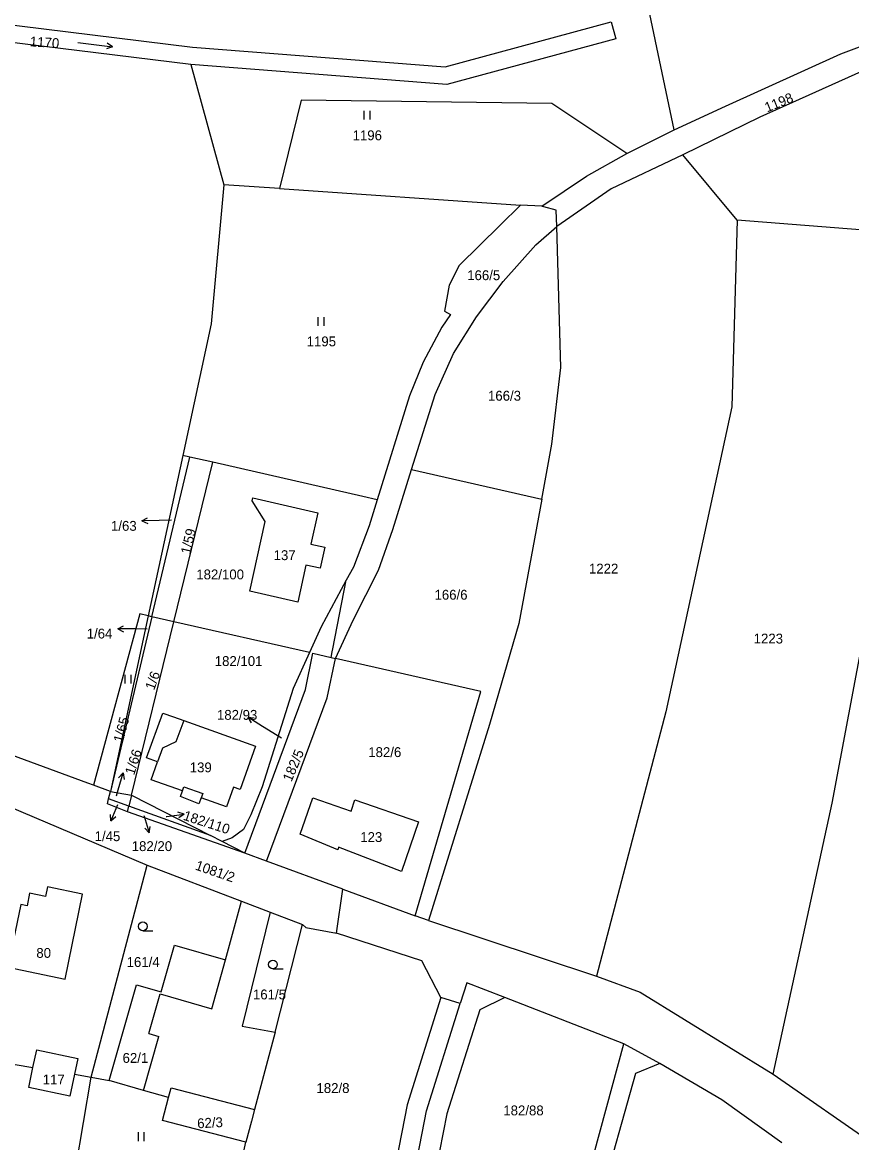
# Model space of a CAD drawing. Extents: x -746176 to -739709, y -1128407 to -1124482.
# Drawn here: x -742008.2 to -741865.4, y -1126433.2 to -1126240.2 of the extents above; entities that cross this region are included whole.
import ezdxf

# ---------------------------------------------------------------- set-up
doc = ezdxf.new("R2010")
doc.units = 0
for name, color, linetype in [('Hranice parcel', 7, 'Continuous'), ('Parcelní čísla', 7, 'Continuous'), ('Pop  PČ popisy', 7, 'Continuous'), ('Vnitřní kresba', 7, 'Continuous'), ('Značky kultur', 7, 'Continuous')]:
    doc.layers.add(name, color=color, linetype=linetype)

msp = doc.modelspace()

# ---------------------------------------------------------------- linework, layer by layer
at = {"layer": 'Hranice parcel'}
for p, q in [((-741979.16, -1126247.44), (-741973.49, -1126268.18)), ((-741904.1, -1126262.78), (-741895.95, -1126258.73)), ((-741885.09, -1126274.27), (-741894.45, -1126263.02)), ((-741963.91, -1126268.84), (-741973.49, -1126268.18)), ((-741963.91, -1126268.84), (-741922.39, -1126271.67)), ((-741918.69, -1126271.87), (-741922.39, -1126271.67)), ((-741856.86, -1126276.54), (-741885.09, -1126274.27)), ((-741980.55, -1126314.84), (-741986.51, -1126342.46)), ((-741985.86, -1126342.61), (-741979.32, -1126315.12)), ((-741982.09, -1126343.47), (-741975.4, -1126316.01)), ((-741979.32, -1126315.12), (-741980.55, -1126314.84)), ((-741975.4, -1126316.01), (-741979.32, -1126315.12)), ((-741941.15, -1126317.27), (-741918.74, -1126322.36)), ((-741951.16, -1126334.05), (-741952.39, -1126336.34)), ((-741952.39, -1126336.34), (-741956.73, -1126344.37)), ((-741986.51, -1126342.46), (-741993.03, -1126372.73)), ((-741985.86, -1126342.61), (-741993.03, -1126372.73)), ((-741989.38, -1126373.38), (-741982.09, -1126343.47)), ((-741985.86, -1126342.61), (-741986.51, -1126342.46)), ((-741982.09, -1126343.47), (-741985.86, -1126342.61)), ((-741958.73, -1126348.77), (-741982.09, -1126343.47)), ((-741954.27, -1126349.79), (-741951.24, -1126343.21)), ((-741956.73, -1126344.37), (-741958.73, -1126348.77)), ((-741955, -1126349.62), (-741954.27, -1126349.79)), ((-741993.03, -1126372.73), (-741995.94, -1126371.66)), ((-741993.33, -1126374), (-741993.03, -1126372.73)), ((-741989.85, -1126375.26), (-741993.33, -1126374)), ((-741993.03, -1126372.73), (-741989.38, -1126373.38)), ((-741989.38, -1126373.38), (-741989.85, -1126375.26)), ((-741989.38, -1126373.38), (-741975.79, -1126380.32)), ((-741990.09, -1126376.24), (-741989.85, -1126375.26)), ((-741969.88, -1126383.35), (-741990.09, -1126376.24)), ((-741975.79, -1126380.32), (-741989.85, -1126375.26)), ((-741973.78, -1126381.35), (-741975.79, -1126380.32)), ((-741972.03, -1126380.69), (-741973.78, -1126381.35)), ((-741969.88, -1126383.35), (-741973.78, -1126381.35)), ((-741966.13, -1126384.73), (-741969.88, -1126383.35)), ((-741996.32, -1126421.94), (-741986.71, -1126385.43)), ((-741986.71, -1126385.43), (-741970.45, -1126391.64)), ((-741953, -1126389.58), (-741966.13, -1126384.73)), ((-741954.07, -1126397.17), (-741953, -1126389.58)), ((-741953, -1126389.58), (-741940.51, -1126394.18)), ((-741970.45, -1126391.64), (-741965.53, -1126393.52)), ((-741965.53, -1126393.52), (-741959.96, -1126395.65)), ((-741964.66, -1126414.2), (-741959.96, -1126395.65)), ((-741938.23, -1126394.97), (-741940.51, -1126394.18)), ((-741938.23, -1126394.97), (-741909.32, -1126404.54)), ((-741932.77, -1126409.29), (-741936.11, -1126408.24)), ((-741904.57, -1126416.23), (-741925.07, -1126408.25)), ((-741964.66, -1126414.2), (-741968.2, -1126427.52)), ((-741898.42, -1126419.6), (-741904.57, -1126416.23)), ((-741999.2, -1126421.47), (-741996.32, -1126421.94)), ((-741999.11, -1126438.17), (-741996.32, -1126421.94)), ((-741996.32, -1126421.94), (-741993.21, -1126422.56)), ((-741878.88, -1126421.46), (-741852.49, -1126439.8)), ((-741971.96, -1126443.41), (-741969.67, -1126433.17))]:
    msp.add_line(p, q, dxfattribs=at)
for points in [[(-741895.95, -1126258.73), (-741902.39, -1126227.83), (-742032.39, -1126201.61)], [(-741979.16, -1126247.44), (-742018.02, -1126242.67), (-742051.56, -1126236.78), (-742071.8, -1126233.98)], [(-742037.23, -1126236.37), (-742017.58, -1126239.71), (-741978.86, -1126244.46), (-741935.37, -1126247.86), (-741906.75, -1126240.11), (-741905.97, -1126243.01), (-741935.09, -1126250.9), (-741979.16, -1126247.44)], [(-741895.95, -1126258.73), (-741887.06, -1126254.64), (-741867.23, -1126245.63), (-741859.7, -1126242.83), (-741853.68, -1126241.82), (-741840.1, -1126242.23)], [(-741841.74, -1126251.46), (-741852.27, -1126246.05), (-741856.49, -1126246.25), (-741862.01, -1126247.91), (-741881.16, -1126256.56), (-741894.45, -1126263.02)], [(-741904.1, -1126262.78), (-741917.02, -1126254.2), (-741960.14, -1126253.61), (-741963.91, -1126268.84)], [(-741918.69, -1126271.87), (-741911.03, -1126266.72), (-741904.1, -1126262.78)], [(-741894.45, -1126263.02), (-741906.75, -1126268.89), (-741916.15, -1126275.4)], [(-741973.49, -1126268.18), (-741975.66, -1126292.15), (-741980.55, -1126314.84)], [(-741922.39, -1126271.67), (-741925.91, -1126275.15), (-741932.95, -1126282.11), (-741934.69, -1126285.47), (-741935.47, -1126289.95), (-741934.45, -1126290.55), (-741935.93, -1126292.73), (-741939.16, -1126298.76), (-741941.48, -1126304.55), (-741947.05, -1126322.45)], [(-741916.15, -1126275.4), (-741916.23, -1126272.57), (-741918.37, -1126271.96), (-741918.69, -1126271.87)], [(-741941.15, -1126317.27), (-741937.11, -1126304.31), (-741933.93, -1126297.28), (-741929.99, -1126290.94), (-741925.39, -1126284.87), (-741919.74, -1126278.55), (-741916.15, -1126275.4)], [(-741918.74, -1126322.36), (-741917, -1126312.88), (-741915.44, -1126299.69), (-741916.15, -1126275.4)], [(-741885.09, -1126274.27), (-741886, -1126306.44), (-741897.34, -1126359), (-741909.32, -1126404.54)], [(-741878.88, -1126421.46), (-741868.71, -1126374.72), (-741857.4, -1126314.53), (-741856.86, -1126276.54)], [(-741947.05, -1126322.45), (-741949.55, -1126321.88), (-741975.4, -1126316.01)], [(-741951.24, -1126343.21), (-741946.82, -1126334.61), (-741944.36, -1126327.59), (-741941.15, -1126317.27)], [(-741969.03, -1126338.22), (-741966.34, -1126326.2), (-741968.61, -1126322.66), (-741968.49, -1126322.14), (-741957.3, -1126324.7), (-741958.52, -1126330.09), (-741956.07, -1126330.63), (-741956.89, -1126334.27), (-741959.34, -1126333.71), (-741960.77, -1126340.08), (-741969.03, -1126338.22)], [(-741947.05, -1126322.45), (-741948.46, -1126326.96), (-741951.16, -1126334.05)], [(-741918.74, -1126322.36), (-741922.66, -1126343.77), (-741927.73, -1126361.18), (-741938.23, -1126394.97)], [(-741955, -1126349.62), (-741954.81, -1126348.66), (-741954.71, -1126348.16), (-741952.39, -1126336.34)], [(-741986.51, -1126342.46), (-741987.96, -1126342.12), (-741995.94, -1126371.66)], [(-741958.73, -1126348.77), (-741961.57, -1126355.01), (-741966.88, -1126371.94), (-741968.84, -1126376.73), (-741970.09, -1126379.3), (-741972.03, -1126380.69)], [(-741969.88, -1126383.35), (-741959.42, -1126355.18), (-741958.17, -1126348.9), (-741955, -1126349.62)], [(-741966.13, -1126384.73), (-741955.67, -1126356.57), (-741954.27, -1126349.79)], [(-741940.51, -1126394.18), (-741929.25, -1126355.48), (-741954.27, -1126349.79)], [(-741977.77, -1126374.86), (-741980.95, -1126373.62), (-741980.61, -1126372.64), (-741986.02, -1126370.7), (-741984.92, -1126367.63), (-741986.82, -1126366.94), (-741984.02, -1126359.21), (-741982.15, -1126359.85), (-741980.39, -1126360.49), (-741968.02, -1126364.9), (-741970.7, -1126372.41), (-741971.84, -1126372), (-741973.03, -1126375.35), (-741977.37, -1126373.8), (-741977.77, -1126374.86)], [(-741995.94, -1126371.66), (-741996.93, -1126371.29), (-742011.08, -1126366.08), (-742011.25, -1126365.95)], [(-742017.65, -1126371.11), (-742017.02, -1126371.6), (-742014.99, -1126373.44), (-741986.71, -1126385.43)], [(-741990.09, -1126376.24), (-741993.53, -1126374.84), (-741993.33, -1126374)], [(-741958.18, -1126373.85), (-741951.58, -1126376.12), (-741950.91, -1126374.18), (-741939.97, -1126377.94), (-741942.91, -1126386.52), (-741953.71, -1126382.33), (-741953.86, -1126382.76), (-741960.32, -1126380.06), (-741958.18, -1126373.85)], [(-742003.87, -1126389.15), (-742004.21, -1126390.8), (-742006.94, -1126390.24), (-742007.38, -1126392.41), (-742008.47, -1126392.19), (-742010.7, -1126403.03), (-742000.83, -1126405.05), (-741997.82, -1126390.4), (-742003.87, -1126389.15)], [(-741993.21, -1126422.56), (-741988.52, -1126406.06), (-741984.26, -1126407.27), (-741981.98, -1126399.24), (-741973.18, -1126401.74), (-741970.45, -1126391.64)], [(-741965.53, -1126393.52), (-741970.31, -1126413.16), (-741964.66, -1126414.2)], [(-741959.96, -1126395.65), (-741959.39, -1126396.19), (-741954.07, -1126397.17)], [(-741936.11, -1126408.24), (-741939.36, -1126401.91), (-741954.07, -1126397.17)], [(-741909.32, -1126404.54), (-741901.76, -1126407.3), (-741878.88, -1126421.46)], [(-741925.07, -1126408.25), (-741931.64, -1126405.69), (-741932.77, -1126409.29)], [(-741954.32, -1126508.73), (-741938.56, -1126427.78), (-741932.77, -1126409.29)], [(-741936.11, -1126408.24), (-741941.9, -1126426.74), (-741946.15, -1126448.52)], [(-741925.07, -1126408.25), (-741929.41, -1126410.36), (-741935.06, -1126428.26), (-741937.58, -1126441.15)], [(-742024.68, -1126414.24), (-742015.91, -1126416.77), (-742016.26, -1126418.65), (-742006.36, -1126420.29)], [(-741912.45, -1126446.2), (-741911.72, -1126442.48), (-741904.57, -1126416.23)], [(-742006.36, -1126420.29), (-742005.72, -1126417.27), (-741998.63, -1126418.76), (-741999.2, -1126421.47)], [(-741999.2, -1126421.47), (-741999.99, -1126425.22), (-742007.08, -1126423.73), (-742006.36, -1126420.29)], [(-741898.42, -1126419.6), (-741902.57, -1126421.34), (-741908.84, -1126443.59), (-741914.46, -1126471.66), (-741921.58, -1126508.41), (-741929.05, -1126550.68), (-741935.86, -1126591.95), (-741938.82, -1126591.67)], [(-741877.38, -1126433.3), (-741887.7, -1126425.84), (-741898.42, -1126419.6)], [(-741983.01, -1126425.46), (-741987.35, -1126424.23), (-741993.21, -1126422.56)], [(-741983.01, -1126425.46), (-741982.58, -1126423.8), (-741968.2, -1126427.52)], [(-741969.67, -1126433.17), (-741984.04, -1126429.45), (-741983.01, -1126425.46)], [(-741968.2, -1126427.52), (-741968.72, -1126429.53), (-741969.67, -1126433.17)]]:
    msp.add_lwpolyline(points, dxfattribs=at)
at = {"layer": 'Pop  PČ popisy'}
for p, q in [((-741987.6, -1126326.08), (-741986.61, -1126325.56)), ((-741984.6, -1126326.03), (-741987.6, -1126326.08)), ((-741987.6, -1126326.08), (-741986.59, -1126326.57)), ((-741982.49, -1126326), (-741984.6, -1126326.03)), ((-741991.75, -1126344.68), (-741990.74, -1126344.19)), ((-741988.75, -1126344.73), (-741991.75, -1126344.68)), ((-741991.75, -1126344.68), (-741990.76, -1126345.2)), ((-741986.71, -1126344.75), (-741988.75, -1126344.73)), ((-741966.82, -1126361.51), (-741969.36, -1126359.92)), ((-741969.36, -1126359.92), (-741968.25, -1126360.03)), ((-741969.36, -1126359.92), (-741968.78, -1126360.88)), ((-741963.58, -1126363.54), (-741966.82, -1126361.51)), ((-741991.68, -1126372.43), (-741990.85, -1126369.54)), ((-741990.85, -1126369.54), (-741991.61, -1126370.37)), ((-741990.85, -1126369.54), (-741990.65, -1126370.65)), ((-741991.98, -1126373.5), (-741991.68, -1126372.43)), ((-741991.82, -1126375.03), (-741992.94, -1126377.81)), ((-741980.33, -1126376.66), (-741981.39, -1126376.29)), ((-741992.94, -1126377.81), (-741993.03, -1126376.7)), ((-741992.94, -1126377.81), (-741992.1, -1126377.07)), ((-741987.25, -1126376.89), (-741987.22, -1126377)), ((-741987.22, -1126377), (-741986.34, -1126379.87)), ((-741983.4, -1126377.04), (-741983.31, -1126377.03)), ((-741983.31, -1126377.03), (-741980.33, -1126376.66)), ((-741980.33, -1126376.66), (-741981.26, -1126377.28)), ((-741986.34, -1126379.87), (-741987.11, -1126379.06)), ((-741986.34, -1126379.87), (-741986.16, -1126378.77))]:
    msp.add_line(p, q, dxfattribs=at)
at = {"layer": 'Vnitřní kresba'}
for p, q in [((-741980.39, -1126360.49), (-741981.73, -1126364.15)), ((-741981.73, -1126364.15), (-741984.06, -1126365.24)), ((-741984.06, -1126365.24), (-741984.92, -1126367.63)), ((-741980.61, -1126372.64), (-741980.36, -1126371.92)), ((-741980.36, -1126371.92), (-741977.1, -1126373.07)), ((-741977.1, -1126373.07), (-741977.37, -1126373.8)), ((-741975.58, -1126410.16), (-741973.18, -1126401.74)), ((-741986.43, -1126414.45), (-741984.48, -1126407.62)), ((-741984.48, -1126407.62), (-741975.58, -1126410.16)), ((-741987.35, -1126424.23), (-741984.7, -1126414.94)), ((-741986.43, -1126414.45), (-741984.7, -1126414.94))]:
    msp.add_line(p, q, dxfattribs=at)
at = {"layer": 'Značky kultur'}
for p, q in [((-741998.62, -1126243.68), (-741992.67, -1126244.41)), ((-741992.67, -1126244.41), (-741993.7, -1126244.78)), ((-741992.67, -1126244.41), (-741993.58, -1126243.79)), ((-741949.31, -1126256.96), (-741949.31, -1126255.46)), ((-741948.31, -1126256.96), (-741948.31, -1126255.46)), ((-741957.22, -1126292.47), (-741957.22, -1126290.97)), ((-741956.22, -1126292.47), (-741956.22, -1126290.97)), ((-741990.47, -1126354.15), (-741990.47, -1126352.65)), ((-741989.47, -1126354.15), (-741989.47, -1126352.65)), ((-741987.45, -1126396.72), (-741985.7, -1126396.72)), ((-741965.03, -1126403.31), (-741963.28, -1126403.31)), ((-741988.21, -1126432.96), (-741988.21, -1126431.46)), ((-741987.21, -1126432.96), (-741987.21, -1126431.46))]:
    msp.add_line(p, q, dxfattribs=at)
for centre in [(-741987.45, -1126395.97), (-741965.03, -1126402.56)]:
    msp.add_circle(centre, 0.75, dxfattribs=at)

# ---------------------------------------------------------------- texts
at = {"layer": 'Parcelní čísla'}
for s, rotation, p in [('1170', 356, (-742006.94, -1126244.31)), ('1198', 22, (-741879.92, -1126255.73)), ('1/59', 77, (-741979.28, -1126331.96)), ('1/6', 70, (-741985.5, -1126355.38)), ('1/65', 75, (-741990.9, -1126364.43)), ('1/66', 72, (-741988.95, -1126370.01)), ('182/5', 67, (-741961.85, -1126371.18)), ('182/110', 342, (-741980.61, -1126377.58)), ('1081/2', 341, (-741978.54, -1126386.16)), ('62/3', 3, (-741978.03, -1126430.78))]:
    msp.add_text(s, height=1.7, rotation=rotation, dxfattribs=at).set_placement(p)
for s, p in [('1196', (-741951.31, -1126260.51)), ('166/5', (-741931.57, -1126284.62)), ('1195', (-741959.22, -1126296.02)), ('166/3', (-741927.99, -1126305.39)), ('1/63', (-741992.92, -1126327.81)), ('137', (-741964.91, -1126332.86)), ('1222', (-741910.6, -1126335.17)), ('182/100', (-741978.23, -1126336.18)), ('166/6', (-741937.2, -1126339.68)), ('1/64', (-741997.11, -1126346.37)), ('1223', (-741882.23, -1126347.23)), ('182/101', (-741975.05, -1126351.11)), ('182/93', (-741974.67, -1126360.38)), ('182/6', (-741948.61, -1126366.8)), ('139', (-741979.36, -1126369.43)), ('1/45', (-741995.74, -1126381.29)), ('123', (-741949.99, -1126381.44)), ('182/20', (-741989.35, -1126383)), ('80', (-742005.78, -1126401.4)), ('161/4', (-741990.23, -1126402.97)), ('161/5', (-741968.47, -1126408.56)), ('62/1', (-741990.93, -1126419.5)), ('117', (-742004.67, -1126423.21)), ('182/8', (-741957.53, -1126424.69)), ('182/88', (-741925.35, -1126428.54))]:
    msp.add_text(s, height=1.7, dxfattribs=at).set_placement(p)

doc.saveas('drawing.dxf')
